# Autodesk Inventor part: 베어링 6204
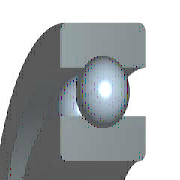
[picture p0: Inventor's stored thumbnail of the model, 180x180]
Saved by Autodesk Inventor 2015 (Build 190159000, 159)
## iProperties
IsCustomPart: 0
Created: 2018-09
Part Number: 베어링 6204
Material: 스테인리스강
Description: 깊은 그루브 볼 베어링
Document SubType Name: Modeling
Standard: KS B 2023
Standards Organization: KS
Language: ko-KR
Size Designation: 6204 - 20 x 47 x 14
Categories: <MemberInstance><Categories><Category DisplayName="샤프트 부품" InternalName="7f7aeb1f-a693-4053-b835-cee3144e0d98" Mnemonic="SHFT"><Category DisplayName="베어링" Inter
Density: 8.08 g/cm^3
Mass: 107.173 g
Surface Area: 87.8912 cm^2
Volume: 13.264 cm^3
Appearance: 노란색
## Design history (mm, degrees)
sketch "스케치" dims "d0" = 7.02 (= -0.26 x WD + 0.26 x BD)
  geometry: L1 (3.49, 16.75)-(10.51, 16.75); L2 (7, 16.75)-(7, 13.24); L3 (7, 16.75)-(7, 20.26); L4 (4.392, 14.401)-(0, 14.401); L5 (0, 10)-(14, 10); L6 (4.392, 19.099)-(0, 19.099); L7 (0, 23.5)-(14, 23.5); L8 (14, 10)-(14, 14.401); L9 (9.608, 14.401)-(14, 14.401); L10 (9.608, 19.099)-(14, 19.099); L11 (14, 23.5)-(14, 19.099); L12 (-1.4, 0)-(8.4, 0) reference; L13 (0, -0.3)-(0, 5.3) reference
  constraints: 22 end point, 4 point on line, 2 collinear, 2 perpendicular, 2 symmetric about line, 1 midpoint, 1 parallel, 14 other
  dimensions: "d9" = 20 diameter of L5 L12 (= WD); "d11" = 47 diameter of L7 L12 (= BD); "d12" = 14 distance between parallel lines of L8 L13 (= KB); "d13" = 28.802 diameter of L9 L12 (= 0.326 x BD + 0.674 x WD)
revolve "본체" stored, may be unused: angle "d6" = 90 deg
revolve "볼" stored, may be unused: angle "d7" = 90 deg
pattern_circular "IDS_ARRAYBALL[SIMPL:T]" dims angle "d3" = 360 deg
body "Solid1"
fillet "모깎기1" dims "d1" = 1 (= KRS)
other parameters: "WD" = 20 [user parameter; used in 5 equation terms], "BD" = 47 [user parameter; used in 5 equation terms], "KB" = 14 [user parameter; used in 1 equation term], "KRS" = 1 [user parameter; used in 1 equation term], "d4" = 0, "d5" = 0, "d8" = 0, "d14" = 0, "d15" = 0, "BBA" = 0 [user parameter], "BC0" = 6550000 [user parameter], "BC" = 1.27e+07 [user parameter], "BR" = 23.5 (= 0.5 x BD) [user parameter]
